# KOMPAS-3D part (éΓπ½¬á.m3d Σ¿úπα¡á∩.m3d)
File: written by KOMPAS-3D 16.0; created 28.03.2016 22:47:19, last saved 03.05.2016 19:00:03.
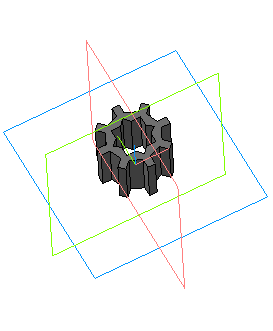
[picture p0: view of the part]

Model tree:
1. Эскиз:1
2. Операция выдавливания:1
     Расстояние 1 = 14
3. Эскиз:2
4. Вырезать элемент выдавливания:1
     Расстояние 1 = 30
5. Массив по концентрической сетке:1  (with: Вырезать элемент выдавливания:1, Эскиз:2)  (8 pattern instances)
     Геометрический массив = 7; Шаг 2 = 360
6. Эскиз:3
7. Вырезать элемент выдавливания:2
     Расстояние 1 = 40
